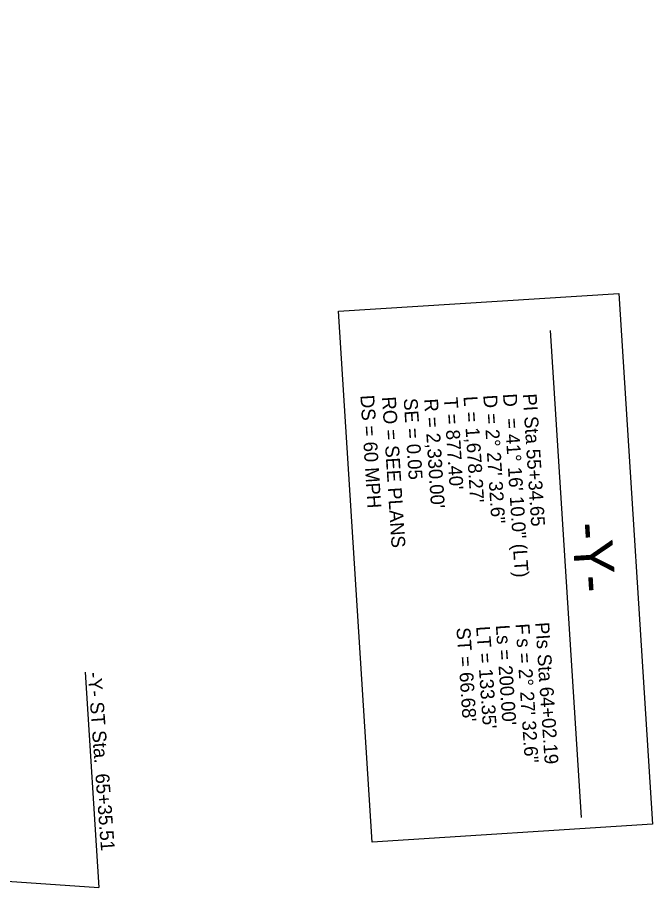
# Model space of a CAD drawing. Extents: x 1778969 to 1790720, y 807089 to 817794.
# Drawn here: x 1781214.6 to 1781536.1, y 811092.9 to 811533.5 of the extents above; entities that cross this region are included whole.
import ezdxf

# ---------------------------------------------------------------- set-up
doc = ezdxf.new("R2010")
doc.units = 0
for name, color, linetype in [('Prop Horizontal Alignment', 7, 'Continuous'), ('Prop Horizontal Alignment Curve and Spiral Data', 7, 'Continuous'), ('Prop Horizontal Alignment Station Label', 7, 'Continuous')]:
    doc.layers.add(name, color=color, linetype=linetype)

msp = doc.modelspace()

# ---------------------------------------------------------------- linework, layer by layer
at = {"layer": 'Prop Horizontal Alignment'}
msp.add_arc((1783308.81, 811525.98), 2330, 144.08998, 185.35942, dxfattribs=at)
at = {"layer": 'Prop Horizontal Alignment Station Label'}
for p, q in [((1781484.23, 811375.04), (1781499.9, 811128.44)), ((1781248.87, 811201.91), (1781255.8, 811092.92)), ((1781014.85, 811110.06), (1781255.8, 811092.92))]:
    msp.add_line(p, q, dxfattribs=at)
msp.add_lwpolyline([(1781519.01, 811393.74), (1781536.08, 811125.02), (1781394.21, 811116), (1781377.13, 811384.73)], close=True, dxfattribs=at)

# ---------------------------------------------------------------- texts
at = {"layer": 'Prop Horizontal Alignment Curve and Spiral Data'}
for s, rotation, p in [('DS = 60 MPH', 273.6756, (1781388.18, 811342.12)), ('D = 2%%d 27\' 32.6"', 273.6756, (1781450.38, 811342.21)), ('D', 273.6756, (1781460.36, 811342.85)), ('PI Sta 55+34.65', 273.6756, (1781470.38, 811342.82)), ('RO = SEE PLANS', 273.6756, (1781399.13, 811341.3)), ('SE = 0.05', 273.6756, (1781410.09, 811340.49)), ("R = 2,330.00'", 273.6756, (1781420.44, 811340.28)), ("T = 877.40'", 273.6756, (1781430.42, 811340.92)), ("L = 1,678.27'", 273.6756, (1781440.4, 811341.56)), ('= 41%%d 16\' 10.0" (LT)', 273.6756, (1781461.27, 811330.47)), ("ST = 66.68'", 273.8283, (1781436.8, 811224.42)), ("LT = 133.35'", 273.8283, (1781446.77, 811225.09)), ("Ls = 200.00'", 273.8283, (1781456.75, 811225.75)), ('F', 273.8283, (1781466.73, 811226.42)), ('PIs Sta 64+02.19', 273.8283, (1781476.71, 811227.09)), ('s = 2%%d 27\' 32.6"', 273.8283, (1781467.23, 811218.92))]:
    msp.add_text(s, height=7, rotation=rotation, dxfattribs=at).set_placement(p)
at = {"layer": 'Prop Horizontal Alignment Station Label'}
for s, height, rotation, p in [('-Y-', 20, 273.6364, (1781495.18, 811277.38)), ('-Y- ST Sta.  65+35.51', 7, 274.2938, (1781250.19, 811201.82))]:
    msp.add_text(s, height=height, rotation=rotation, dxfattribs=at).set_placement(p)

doc.saveas('drawing.dxf')
